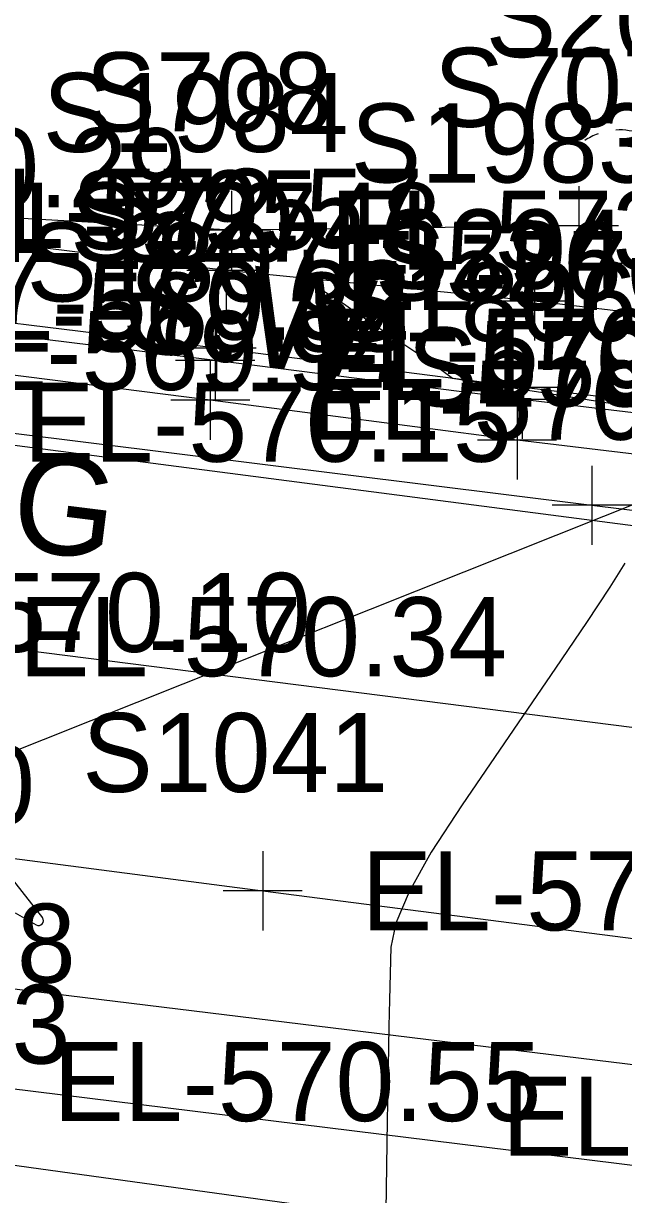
# Model space of a CAD drawing. Extents: x 1724534 to 1727318, y 657156 to 660047.
# Drawn here: x 1725795.9 to 1725826.2, y 658568.3 to 658627.5 of the extents above; entities that cross this region are included whole.
import ezdxf

# ---------------------------------------------------------------- set-up
doc = ezdxf.new("R2010")
doc.units = 0
for name, color, linetype in [('SURVEY - CENTERLINE - Preliminary Text', 7, 'Continuous'), ('SURVEY - CONTOURS - Intermediate with optional Text', 7, 'Continuous'), ('SURVEY - DRAINAGE - Area Shapes', 7, 'Continuous'), ('SURVEY - DRAINAGE - Storm Sewer', 7, 'Continuous'), ('SURVEY - DTM - Breaklines', 7, 'Continuous'), ('SURVEY - DTM - Breaklines - Points - Elevations', 7, 'Continuous'), ('SURVEY - DTM - Breaklines - Points - Locators', 7, 'Continuous'), ('SURVEY - DTM - Breaklines - Points - Numbers', 7, 'Continuous'), ('SURVEY - ROADSIDE BARRIERS - Points - Elevations', 7, 'Continuous'), ('SURVEY - ROADSIDE BARRIERS - Points - Locators', 7, 'Continuous'), ('SURVEY - ROADSIDE BARRIERS - Points - Numbers', 7, 'Continuous'), ('SURVEY - ROADSIDE BARRIERS with Text', 7, 'Continuous'), ('SURVEY - TRAFFIC CONTROL - Pavement Marking - Points - Elevations', 7, 'Continuous'), ('SURVEY - TRAFFIC CONTROL - Pavement Marking - Points - Locators', 7, 'Continuous'), ('SURVEY - TRAFFIC CONTROL - Pavement Marking - Points - Numbers', 7, 'Continuous'), ('SURVEY - TRAFFIC CONTROL - Pavement Marking with Text', 7, 'Continuous'), ('SURVEY - TRAFFIC CONTROL - Signs - Points - Elevations', 7, 'Continuous'), ('SURVEY - TRANSPORTATION - Features', 7, 'Continuous'), ('SURVEY - TRANSPORTATION - Features - Points - Elevations', 7, 'Continuous'), ('SURVEY - TRANSPORTATION - Features - Points - Locators', 7, 'Continuous'), ('SURVEY - TRANSPORTATION - Features - Points - Numbers', 7, 'Continuous'), ('SURVEY - TRANSPORTATION - Features Text', 7, 'Continuous'), ('SURVEY - TRANSPORTATION - Roads', 7, 'Continuous'), ('SURVEY - TRANSPORTATION - Roads - Points - Elevations', 7, 'Continuous'), ('SURVEY - TRANSPORTATION - Roads - Points - Locators', 7, 'Continuous'), ('SURVEY - TRANSPORTATION - Roads - Points - Numbers', 7, 'Continuous'), ('SURVEY - UTILITIES - Poles and Miscellaneous - Points - Numbers', 7, 'Continuous'), ('SURVEY - UTILITIES - Poles and Miscellaneous with Text', 7, 'Continuous'), ('SURVEY - UTILITIES - Water with Text', 7, 'Continuous')]:
    doc.layers.add(name, color=color, linetype=linetype)

msp = doc.modelspace()

# ---------------------------------------------------------------- linework, layer by layer
at = {"layer": 'SURVEY - CENTERLINE - Preliminary Text'}
msp.add_line((1725772.853, 658581.708), (1725925.415, 658642.543), dxfattribs=at)
at = {"layer": 'SURVEY - CONTOURS - Intermediate with optional Text'}
for points in [[(1725809.975, 658614.638), (1725811.149, 658613.928), (1725811.417, 658613.762), (1725811.716, 658613.57), (1725812.047, 658613.35), (1725812.41, 658613.104), (1725813.791, 658612.158), (1725814.148, 658611.917), (1725814.489, 658611.69), (1725815.664, 658610.92), (1725815.966, 658610.721), (1725816.236, 658610.538), (1725816.475, 658610.372), (1725816.681, 658610.223), (1725817.568, 658609.566), (1725819.597, 658609.247), (1725820.301, 658609.137), (1725821.1, 658609.013), (1725821.152, 658609.005), (1725821.152, 658609.005), (1725822.579, 658608.776), (1725825.537, 658608.303), (1725826.087, 658608.215), (1725826.634, 658608.127)], [(1725826.282, 658600.218), (1725825.518, 658598.99), (1725824.351, 658597.216), (1725822.779, 658594.895), (1725818.049, 658587.977), (1725816.493, 658585.581), (1725815.375, 658583.585), (1725814.694, 658581.986), (1725814.449, 658580.786), (1725814.38, 658578.117), (1725814.351, 658576.769), (1725814.314, 658574.729), (1725814.269, 658571.996), (1725814.216, 658568.57), (1725814.066, 658558.51)]]:
    msp.add_lwpolyline(points, dxfattribs=at)
at = {"layer": 'SURVEY - DRAINAGE - Area Shapes'}
msp.add_lwpolyline([(1725876.527, 658537.521), (1725880.453, 658568.253), (1725462.782, 658619.36), (1725459.014, 658588.567)], close=True, dxfattribs=at)
at = {"layer": 'SURVEY - DRAINAGE - Storm Sewer'}
msp.add_lwpolyline([(1725899.594, 658555.371), (1725464.565, 658615.304), (1725129.381, 658652.795)], dxfattribs=at)
at = {"layer": 'SURVEY - DTM - Breaklines'}
msp.add_lwpolyline([(1725923.442, 658596.261), (1725920.349, 658596.664), (1725900.537, 658599.315), (1725880.703, 658601.788), (1725860.867, 658604.256), (1725841.017, 658606.73), (1725821.164, 658609.108), (1725805.637, 658611.084), (1725785.8, 658613.524), (1725762.697, 658616.458), (1725748.853, 658618.143), (1725745.613, 658618.535), (1725725.762, 658620.955), (1725705.909, 658623.419), (1725686.061, 658625.875)], dxfattribs=at)
at = {"layer": 'SURVEY - DTM - Breaklines - Points - Locators'}
for p, q in [((1725805.637, 658613.084), (1725805.637, 658609.084)), ((1725807.637, 658611.084), (1725803.637, 658611.084)), ((1725821.164, 658611.108), (1725821.164, 658607.108)), ((1725823.164, 658609.108), (1725819.164, 658609.108))]:
    msp.add_line(p, q, dxfattribs=at)
at = {"layer": 'SURVEY - ROADSIDE BARRIERS - Points - Locators'}
for p, q in [((1725806.38, 658619.061), (1725806.38, 658615.061)), ((1725823.955, 658619.289), (1725823.955, 658615.289)), ((1725808.38, 658617.061), (1725804.38, 658617.061)), ((1725825.955, 658617.289), (1725821.955, 658617.289))]:
    msp.add_line(p, q, dxfattribs=at)
at = {"layer": 'SURVEY - ROADSIDE BARRIERS with Text'}
msp.add_lwpolyline([(1725823.955, 658617.289), (1725806.38, 658617.061), (1725786.387, 658618.168), (1725763.259, 658620.903), (1725749.415, 658622.587), (1725746.173, 658622.967)], dxfattribs=at)
at = {"layer": 'SURVEY - TRAFFIC CONTROL - Pavement Marking - Points - Locators'}
for p, q in [((1725807.969, 658585.629), (1725807.969, 658581.629)), ((1725809.969, 658583.629), (1725805.969, 658583.629))]:
    msp.add_line(p, q, dxfattribs=at)
at = {"layer": 'SURVEY - TRAFFIC CONTROL - Pavement Marking with Text'}
for p, q in [((1725794.745, 658584.93), (1725796.825, 658582.269)), ((1725795.44, 658582.509), (1725796.51, 658581.904))]:
    msp.add_line(p, q, dxfattribs=at)
for points in [[(1725469.93, 658636.195), (1725476.311, 658635.371), (1725478.295, 658635.122), (1725516.011, 658630.481), (1725599.369, 658620.164), (1725678.757, 658610.338), (1725738.298, 658602.97), (1725780.716, 658597.719), (1725790.639, 658596.491), (1725852.127, 658588.674), (1725871.961, 658586.151), (1725916.153, 658580.463)], [(1725691.276, 658598.614), (1725717.028, 658595.036), (1725719.009, 658594.766), (1725742.941, 658591.917), (1725766.76, 658588.985), (1725807.969, 658583.629), (1725837.716, 658579.798), (1725859.541, 658577.092), (1725887.31, 658573.624), (1725917.054, 658569.88)], [(1725753.893, 658578.677), (1725768.555, 658576.886), (1725792.375, 658573.977), (1725838.021, 658568.345), (1725840.005, 658568.1), (1725897.548, 658561.116), (1725916.187, 658558.855)]]:
    msp.add_lwpolyline(points, dxfattribs=at)
msp.add_arc((1725796.631, 658582.118), 0.246, 240.57811, 38.02638, dxfattribs=at)
at = {"layer": 'SURVEY - TRANSPORTATION - Features'}
for points in [[(1725923.364, 658595.652), (1725920.271, 658596.054), (1725900.459, 658598.705), (1725880.625, 658601.178), (1725860.79, 658603.646), (1725840.941, 658606.12), (1725821.088, 658608.498), (1725805.562, 658610.474), (1725785.723, 658612.914), (1725762.62, 658615.849), (1725748.776, 658617.533), (1725745.535, 658617.925), (1725725.684, 658620.345), (1725705.833, 658622.809), (1725685.985, 658625.265)], [(1725924.124, 658601.632), (1725920.917, 658601.133), (1725901.098, 658603.73), (1725881.263, 658606.193), (1725861.425, 658608.639), (1725841.56, 658611.106), (1725821.706, 658613.473), (1725806.126, 658615.02), (1725786.298, 658617.46), (1725763.169, 658620.191), (1725751.211, 658621.652), (1725751.19, 658622.534), (1725749.441, 658623.208)], [(1725923.129, 658593.802), (1725920.036, 658594.204), (1725900.224, 658596.854), (1725880.377, 658599.224), (1725860.524, 658601.554), (1725840.686, 658604.065), (1725820.833, 658606.443), (1725805.311, 658608.457), (1725785.478, 658610.975), (1725762.374, 658613.908), (1725762.62, 658615.849)]]:
    msp.add_lwpolyline(points, dxfattribs=at)
at = {"layer": 'SURVEY - TRANSPORTATION - Features - Points - Locators'}
for p, q in [((1725806.126, 658617.02), (1725806.126, 658613.02)), ((1725821.706, 658615.473), (1725821.706, 658611.473)), ((1725808.126, 658615.02), (1725804.126, 658615.02)), ((1725823.706, 658613.473), (1725819.706, 658613.473)), ((1725805.562, 658612.474), (1725805.562, 658608.474)), ((1725807.562, 658610.474), (1725803.562, 658610.474)), ((1725821.088, 658610.498), (1725821.088, 658606.498)), ((1725805.311, 658610.457), (1725805.311, 658606.457)), ((1725807.311, 658608.457), (1725803.311, 658608.457)), ((1725823.088, 658608.498), (1725819.088, 658608.498)), ((1725820.833, 658608.443), (1725820.833, 658604.443)), ((1725822.833, 658606.443), (1725818.833, 658606.443))]:
    msp.add_line(p, q, dxfattribs=at)
at = {"layer": 'SURVEY - TRANSPORTATION - Roads'}
msp.add_lwpolyline([(1725603.861, 658630.44), (1725726.921, 658615.268), (1725763.101, 658610.806), (1725790.88, 658607.344), (1725824.612, 658603.138), (1725872.227, 658597.261), (1725926.076, 658590.615)], dxfattribs=at)
at = {"layer": 'SURVEY - TRANSPORTATION - Roads - Points - Locators'}
for p, q in [((1725824.612, 658605.138), (1725824.612, 658601.138)), ((1725826.612, 658603.138), (1725822.612, 658603.138))]:
    msp.add_line(p, q, dxfattribs=at)
at = {"layer": 'SURVEY - UTILITIES - Poles and Miscellaneous with Text'}
for start, end in [(110.36251, 124.25193), (68.73872, 93.50876)]:
    msp.add_arc((1725826.014, 658619.01), 3.125, start, end, dxfattribs=at)
at = {"layer": 'SURVEY - UTILITIES - Water with Text'}
msp.add_lwpolyline([(1725847.724, 658579.712), (1725846.548, 658599.52), (1725380.522, 658660.104)], dxfattribs=at)

# ---------------------------------------------------------------- texts
at = {"layer": 'SURVEY - DTM - Breaklines - Points - Elevations'}
for s, p in [('EL-570.32', (1725790.8, 658611.524)), ('EL-570.72', (1725810.637, 658609.084))]:
    msp.add_text(s, height=4, dxfattribs=at).set_placement(p)
at = {"layer": 'SURVEY - DTM - Breaklines - Points - Numbers'}
for s, p in [('S295', (1725798.301, 658616.084)), ('S294', (1725813.828, 658614.108))]:
    msp.add_text(s, height=4, dxfattribs=at).set_placement(p)
at = {"layer": 'SURVEY - ROADSIDE BARRIERS - Points - Elevations'}
for s, p in [('EL-572.57', (1725791.387, 658616.168)), ('EL-573.06', (1725811.38, 658615.061))]:
    msp.add_text(s, height=4, dxfattribs=at).set_placement(p)
at = {"layer": 'SURVEY - ROADSIDE BARRIERS - Points - Numbers'}
for s, p in [('S708', (1725798.997, 658622.061)), ('S707', (1725816.619, 658622.289))]:
    msp.add_text(s, height=4, dxfattribs=at).set_placement(p)
at = {"layer": 'SURVEY - TRAFFIC CONTROL - Pavement Marking - Points - Elevations'}
for s, p in [('EL-570.10', (1725785.716, 658595.719)), ('EL-570.34', (1725795.639, 658594.491)), ('EL-569.90', (1725771.76, 658586.985)), ('EL-570.84', (1725812.969, 658581.629)), ('EL-570.13', (1725773.555, 658574.886)), ('EL-570.55', (1725797.375, 658571.977)), ('EL-572.28', (1725820.075, 658570.219))]:
    msp.add_text(s, height=4, dxfattribs=at).set_placement(p)
at = {"layer": 'SURVEY - TRAFFIC CONTROL - Pavement Marking - Points - Numbers'}
for s, p in [('S1041', (1725798.839, 658588.629)), ('S1048', (1725783.04, 658578.977))]:
    msp.add_text(s, height=4, dxfattribs=at).set_placement(p)
at = {"layer": 'SURVEY - TRAFFIC CONTROL - Signs - Points - Elevations'}
msp.add_text('EL-570.29', height=4, dxfattribs=at).set_placement((1725779.406, 658618.223))
at = {"layer": 'SURVEY - TRANSPORTATION - Features - Points - Elevations'}
for s, p in [('EL-570.48', (1725792.298, 658615.46)), ('EL-570.92', (1725812.126, 658613.02)), ('EL-569.83', (1725790.723, 658610.914)), ('EL-569.94', (1725790.478, 658608.975)), ('EL-570.24', (1725810.562, 658608.474)), ('EL-570.38', (1725810.311, 658606.457))]:
    msp.add_text(s, height=4, dxfattribs=at).set_placement(p)
at = {"layer": 'SURVEY - TRANSPORTATION - Features - Points - Numbers'}
for s, p in [('S1984', (1725796.838, 658621.02)), ('S1983', (1725812.418, 658619.473)), ('S527', (1725798.226, 658615.474)), ('S1807', (1725796.023, 658613.457)), ('S526', (1725813.642, 658613.498)), ('S1806', (1725811.435, 658611.443))]:
    msp.add_text(s, height=4, dxfattribs=at).set_placement(p)
at = {"layer": 'SURVEY - TRANSPORTATION - Features Text'}
for s, rotation, p in [('S.W.', 352.9884, (1725800.674, 658611.075)), ('C&G', 352.89524, (1725785.871, 658602.122))]:
    msp.add_text(s, height=5, rotation=rotation, dxfattribs=at).set_placement(p)
at = {"layer": 'SURVEY - TRANSPORTATION - Roads - Points - Elevations'}
msp.add_text('EL-570.15', height=4, dxfattribs=at).set_placement((1725795.88, 658605.344))
at = {"layer": 'SURVEY - TRANSPORTATION - Roads - Points - Numbers'}
for s, p in [('S1587', (1725781.592, 658612.344)), ('S1588', (1725815.277, 658608.138))]:
    msp.add_text(s, height=4, dxfattribs=at).set_placement(p)
at = {"layer": 'SURVEY - UTILITIES - Poles and Miscellaneous - Points - Numbers'}
msp.add_text('S2053', height=4, dxfattribs=at).set_placement((1725819.245, 658625.816))

doc.saveas('drawing.dxf')
